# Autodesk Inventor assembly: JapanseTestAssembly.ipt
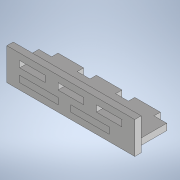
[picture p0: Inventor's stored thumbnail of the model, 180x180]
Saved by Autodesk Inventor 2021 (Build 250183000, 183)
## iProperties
Created: 2026-10
Part Number: JapanseTestAssembly.ipt
Document SubType Name: Assembly
Designer: hp
Author: hp
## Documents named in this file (3)
- C:\Users\hp\Documents\Inventor\DOM1_CartesianRobot\JapanseTestAssembly.ipt.iam
- C:\Users\hp\Documents\Inventor\DOM1_CartesianRobot\JapanseTestBase.ipt
- C:\Users\hp\Documents\Inventor\DOM1_CartesianRobot\JapaneseTestPart.ipt
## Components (2 placed, 2 different names)
1. JapanseTestBase:1 — Mate:1, Flush:1, Mate:2
2. JapaneseTestPart:1 — Mate:1, Flush:1, Mate:2
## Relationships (3: Mate 2, Flush 1)
- Mate:1: JapanseTestBase:1 ↔ JapaneseTestPart:1
- Flush:1: JapanseTestBase:1 ↔ JapaneseTestPart:1
- Mate:2: JapanseTestBase:1 ↔ JapaneseTestPart:1
